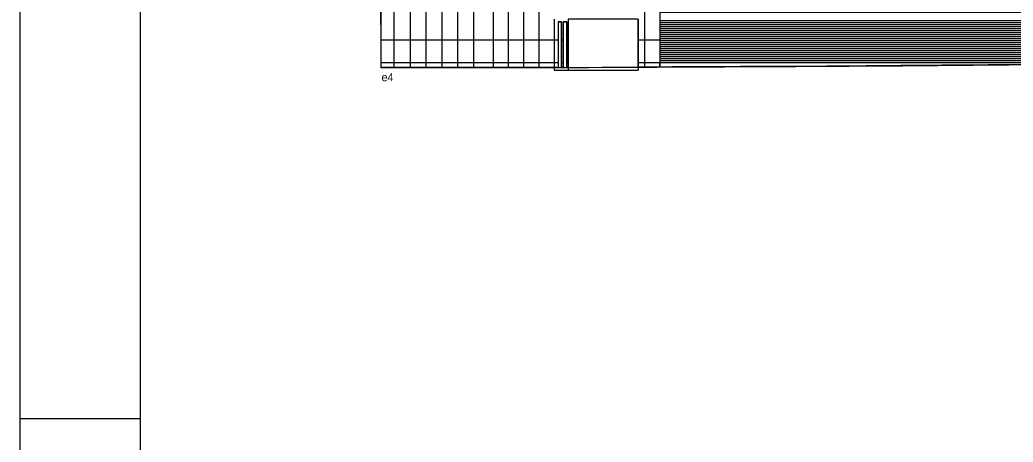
# Model space of a CAD drawing. Extents: x -4333 to -3435, y 16386 to 16556.
# Drawn here: x -3672.72 to -3623.1, y 16444.11 to 16465.23 of the extents above; entities that cross this region are included whole.
import ezdxf

# ---------------------------------------------------------------- set-up
doc = ezdxf.new("R2010")
doc.units = 0
for name, color, linetype in [('Level 1', 7, 'Continuous'), ('Level 17', 7, 'Continuous'), ('Level 2', 7, 'Continuous'), ('Level 25', 7, 'Continuous'), ('Level 60', 7, 'Continuous'), ('Level 63', 7, 'Continuous'), ('Level 7', 7, 'Continuous')]:
    doc.layers.add(name, color=color, linetype=linetype)

msp = doc.modelspace()

# ---------------------------------------------------------------- linework, layer by layer
at = {"layer": 'Level 1'}
for p, q in [((-3666.718, 16504.696), (-3666.718, 16385.896)), ((-3648.408, 16462.837), (-3654.69, 16462.837)), ((-3672.718, 16445.296), (-3666.718, 16445.296))]:
    msp.add_line(p, q, dxfattribs=at)
msp.add_lwpolyline([(-3672.718, 16385.896), (-3435.118, 16385.896), (-3435.118, 16504.696), (-3672.718, 16504.696)], close=True, dxfattribs=at)
msp.add_lwpolyline([(-3672.718, 16385.896), (-3435.118, 16385.896), (-3435.118, 16504.696), (-3672.718, 16504.696)], close=True, dxfattribs=at)
msp.add_spline([(-3648.408, 16462.837), (-3637.5, 16462.887), (-3623.318, 16462.987), (-3615.421, 16463.087), (-3602.963, 16463.207), (-3587.961, 16463.347), (-3587.581, 16463.347)], degree=3, dxfattribs=at)
at = {"layer": 'Level 17'}
for points in [[(-3593.196, 16465.605), (-3640.756, 16465.582), (-3640.755, 16462.919), (-3640.756, 16462.872), (-3641.19, 16462.87), (-3641.564, 16462.868), (-3641.842, 16462.867), (-3641.842, 16465.257), (-3645.325, 16465.257), (-3645.325, 16462.851), (-3645.401, 16462.851), (-3645.401, 16465.137), (-3645.575, 16465.137), (-3645.575, 16462.85), (-3645.66, 16462.85), (-3645.66, 16465.137), (-3645.835, 16465.137), (-3645.835, 16462.849), (-3654.669, 16462.849), (-3654.69, 16467.143), (-3573.699, 16467.143)], [(-3621.027, 16463.014), (-3624.348, 16462.977), (-3626.659, 16462.957), (-3628.72, 16462.941), (-3630.438, 16462.928), (-3632.425, 16462.915), (-3636.729, 16462.891), (-3638.557, 16462.882), (-3640.133, 16462.875), (-3640.756, 16462.872), (-3640.756, 16463.105), (-3622.125, 16463.105)]]:
    msp.add_lwpolyline(points, dxfattribs=at)
at = {"layer": 'Level 25'}
for p, q in [((-3647.563, 16488.811), (-3647.563, 16462.841)), ((-3652.437, 16485.809), (-3652.437, 16462.837)), ((-3650.859, 16485.809), (-3650.859, 16462.837)), ((-3654.037, 16468.015), (-3654.037, 16462.837)), ((-3649.085, 16468.046), (-3649.085, 16462.837)), ((-3640.756, 16468.046), (-3640.756, 16462.872)), ((-3653.224, 16467.764), (-3653.224, 16462.837)), ((-3651.648, 16467.764), (-3651.648, 16462.837)), ((-3650.065, 16467.764), (-3650.065, 16462.837)), ((-3648.326, 16467.764), (-3648.326, 16462.837)), ((-3646.799, 16467.764), (-3646.799, 16462.844)), ((-3641.521, 16467.764), (-3641.521, 16462.869)), ((-3654.69, 16464.227), (-3646.036, 16464.227)), ((-3646.036, 16464.227), (-3645.835, 16464.227)), ((-3645.66, 16464.227), (-3645.575, 16464.227)), ((-3645.401, 16464.227), (-3645.325, 16464.227)), ((-3641.842, 16464.227), (-3640.756, 16464.227)), ((-3654.69, 16463.105), (-3646.036, 16463.105)), ((-3646.036, 16463.105), (-3645.835, 16463.105)), ((-3645.66, 16463.105), (-3645.575, 16463.105)), ((-3645.401, 16463.105), (-3645.325, 16463.105)), ((-3641.842, 16463.105), (-3622.125, 16463.105))]:
    msp.add_line(p, q, dxfattribs=at)
at = {"layer": 'Level 60'}
msp.add_lwpolyline([(-3672.721, 16385.894), (-3435.121, 16385.894), (-3435.121, 16504.694), (-3672.721, 16504.694)], close=True, dxfattribs=at)
at = {"layer": 'Level 63'}
for p, q in [((-3646.036, 16465.257), (-3646.036, 16462.848)), ((-3645.835, 16465.137), (-3645.835, 16462.849)), ((-3645.835, 16465.137), (-3645.66, 16465.137)), ((-3645.66, 16465.137), (-3645.66, 16462.85)), ((-3645.575, 16465.137), (-3645.575, 16462.85)), ((-3645.575, 16465.137), (-3645.401, 16465.137)), ((-3645.401, 16465.137), (-3645.401, 16462.851)), ((-3645.325, 16465.257), (-3645.325, 16462.851)), ((-3641.842, 16465.257), (-3641.842, 16462.867)), ((-3640.756, 16465.205), (-3593.189, 16465.205)), ((-3640.756, 16465.105), (-3593.189, 16465.105)), ((-3640.756, 16465.005), (-3593.189, 16465.005)), ((-3640.756, 16464.905), (-3593.189, 16464.905)), ((-3640.756, 16464.805), (-3593.189, 16464.805)), ((-3640.756, 16464.705), (-3593.189, 16464.705)), ((-3640.756, 16464.605), (-3593.189, 16464.605)), ((-3640.756, 16464.505), (-3593.189, 16464.505)), ((-3640.756, 16464.405), (-3593.189, 16464.405)), ((-3640.756, 16464.305), (-3593.189, 16464.305)), ((-3640.756, 16464.205), (-3593.189, 16464.205)), ((-3640.756, 16464.105), (-3593.189, 16464.105)), ((-3640.756, 16464.005), (-3593.189, 16464.005)), ((-3640.756, 16463.905), (-3593.189, 16463.905)), ((-3640.756, 16463.805), (-3593.189, 16463.805)), ((-3640.756, 16463.705), (-3593.189, 16463.705)), ((-3640.756, 16463.605), (-3593.189, 16463.605)), ((-3640.756, 16463.505), (-3595.171, 16463.505)), ((-3640.756, 16463.405), (-3609.111, 16463.405)), ((-3640.756, 16463.305), (-3609.379, 16463.305)), ((-3640.756, 16463.205), (-3622.125, 16463.205))]:
    msp.add_line(p, q, dxfattribs=at)
at = {"layer": 'Level 7'}
for p, q in [((-3654.69, 16467.143), (-3654.69, 16462.837)), ((-3646.036, 16462.848), (-3646.036, 16462.707)), ((-3646.036, 16462.707), (-3641.842, 16462.707)), ((-3645.325, 16462.851), (-3645.325, 16462.707)), ((-3641.842, 16462.867), (-3641.842, 16462.707))]:
    msp.add_line(p, q, dxfattribs=at)

# ---------------------------------------------------------------- texts
at = {"layer": 'Level 2'}
msp.add_text('e4', height=0.4, rotation=0.1068, dxfattribs=at).set_placement((-3654.654, 16462.16))

doc.saveas('drawing.dxf')
